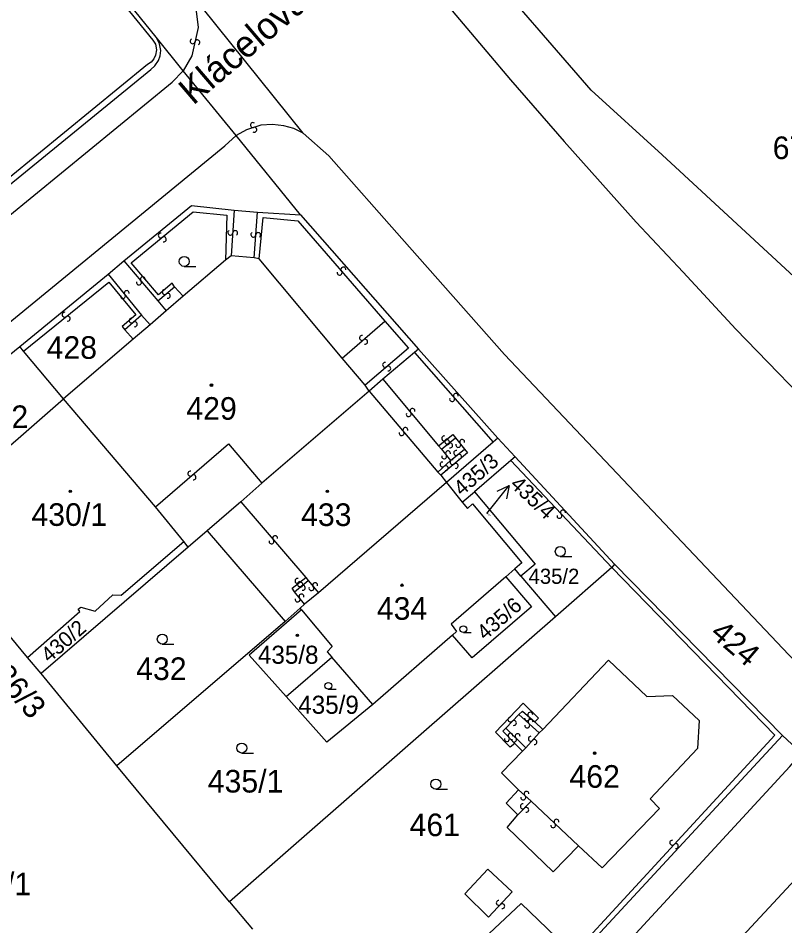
# Model space of a CAD drawing. Extents: x -600391 to -599491, y -1160176 to -1159402.
# Drawn here: x -599909.8 to -599852.1, y -1159960.8 to -1159892.6 of the extents above; entities that cross this region are included whole.
import ezdxf

# ---------------------------------------------------------------- set-up
doc = ezdxf.new("R2010")
doc.units = 0
for name, color, linetype in [('Level 1', 7, 'Continuous'), ('Level 11', 7, 'Continuous'), ('Level 13', 7, 'Continuous'), ('Level 3', 7, 'Continuous'), ('Level 4', 7, 'Continuous'), ('Level 5', 7, 'Continuous'), ('Level 57', 7, 'Continuous')]:
    doc.layers.add(name, color=color, linetype=linetype)

msp = doc.modelspace()

# ---------------------------------------------------------------- linework, layer by layer
at = {"layer": 'Level 1'}
for points in [[(-599773.09, -1160009.38), (-599799.04, -1159987.23), (-599829.62, -1159961.28), (-599837.47, -1159954.27), (-599840.96, -1159951.06), (-599849.35, -1159942.91), (-599851.83, -1159940.43), (-599873.22, -1159917.84), (-599880.94, -1159909.13), (-599886.42, -1159902.9), (-599888.35, -1159901.21), (-599897.08, -1159890.32), (-599918.8, -1159863.43), (-599945.39, -1159830.39)], [(-599904.11, -1159859.22), (-599903.7, -1159859.73), (-599903.4, -1159859.92), (-599878.1, -1159890.84), (-599872.76, -1159897.2), (-599868.72, -1159901.82), (-599863.32, -1159907.89), (-599859.78, -1159911.65), (-599855.8, -1159915.94), (-599848.61, -1159923.35), (-599842.97, -1159928.9)], [(-599899.43, -1159893.99), (-599912.29, -1159878.13), (-599923.65, -1159864.17), (-599926.4, -1159861.06)], [(-599838.86, -1159923.6), (-599861.36, -1159902.83), (-599866.69, -1159897.96), (-599875.35, -1159887.96), (-599866.16, -1159877.35), (-599863.83, -1159879.55), (-599846.25, -1159894.82), (-599845.04, -1159893.23)], [(-599888.35, -1159901.21), (-599897.08, -1159890.32)], [(-599966.31, -1159950.82), (-599928.23, -1159919.57), (-599926.91, -1159918.5), (-599899.82, -1159896.42), (-599899.51, -1159896.14), (-599899.24, -1159895.74), (-599899.13, -1159895.39), (-599899.08, -1159894.99), (-599899.17, -1159894.48), (-599899.43, -1159893.99)], [(-599897.38, -1159896.51), (-599899.43, -1159893.99)], [(-599893.41, -1159901.39), (-599897.38, -1159896.51)], [(-599888.56, -1159907.34), (-599893.41, -1159901.39)], [(-599888.35, -1159901.21), (-599886.42, -1159902.9), (-599880.94, -1159909.13), (-599873.22, -1159917.84), (-599851.83, -1159940.43), (-599849.35, -1159942.91)], [(-599901.85, -1159910.79), (-599896.77, -1159906.65), (-599893.55, -1159906.98)], [(-599893.55, -1159906.98), (-599891.8, -1159907.13)], [(-599891.8, -1159907.13), (-599888.56, -1159907.34)], [(-599888.56, -1159907.34), (-599879.68, -1159917.45)], [(-599893.78, -1159910.43), (-599894.2, -1159910.76)], [(-599892.06, -1159910.57), (-599893.78, -1159910.43)], [(-599891.67, -1159910.64), (-599892.06, -1159910.57)], [(-599885.43, -1159918.13), (-599891.67, -1159910.64)], [(-599903.04, -1159911.8), (-599901.85, -1159910.79)], [(-599894.2, -1159910.76), (-599897.38, -1159913.46)], [(-599909.67, -1159917.25), (-599903.04, -1159911.8)], [(-599897.38, -1159913.46), (-599898.68, -1159914.56)], [(-599898.68, -1159914.56), (-599899.88, -1159915.62)], [(-599899.88, -1159915.62), (-599901.15, -1159916.7)], [(-599901.15, -1159916.7), (-599906.39, -1159921.18)], [(-599917.1, -1159923.33), (-599913.73, -1159920.54), (-599913.44, -1159920.29), (-599911.95, -1159919.06), (-599909.67, -1159917.25)], [(-599909.4, -1159917.59), (-599909.67, -1159917.25)], [(-599879.68, -1159917.45), (-599879.99, -1159917.7)], [(-599879.68, -1159917.45), (-599873.71, -1159924.14)], [(-599906.39, -1159921.18), (-599909.4, -1159917.59)], [(-599883.7, -1159920.14), (-599885.43, -1159918.13)], [(-599879.99, -1159917.7), (-599882.38, -1159919.71)], [(-599883.39, -1159920.59), (-599883.7, -1159920.14)], [(-599882.38, -1159919.71), (-599883.39, -1159920.59)], [(-599883.39, -1159920.59), (-599891.48, -1159927.53)], [(-599913.62, -1159927.46), (-599906.39, -1159921.18)], [(-599899.48, -1159929.31), (-599906.39, -1159921.18)], [(-599873.71, -1159924.14), (-599874.06, -1159924.44)], [(-599873.71, -1159924.14), (-599872.42, -1159925.53)], [(-599874.06, -1159924.44), (-599877.59, -1159927.48)], [(-599872.42, -1159925.53), (-599872.75, -1159925.82)], [(-599872.42, -1159925.53), (-599864.95, -1159933.61)], [(-599872.75, -1159925.82), (-599875.47, -1159928.16)], [(-599891.48, -1159927.53), (-599893.06, -1159928.93)], [(-599877.59, -1159927.48), (-599887.21, -1159935.76)], [(-599877.59, -1159927.48), (-599876.39, -1159928.95)], [(-599876.39, -1159928.95), (-599875.47, -1159928.16)], [(-599875.47, -1159928.16), (-599870.91, -1159933.6), (-599871.99, -1159934.5)], [(-599893.06, -1159928.93), (-599895.58, -1159931.11)], [(-599876.39, -1159928.95), (-599876, -1159929.42), (-599875.62, -1159929.08), (-599871.9, -1159933.51), (-599872.43, -1159933.97)], [(-599897.34, -1159931.91), (-599899.48, -1159929.31)], [(-599895.58, -1159931.11), (-599897.01, -1159932.33)], [(-599895.58, -1159931.11), (-599889.72, -1159937.92)], [(-599909.09, -1159940.63), (-599905.16, -1159937.16), (-599905.3, -1159937), (-599905.09, -1159936.83), (-599904, -1159937.15), (-599902.68, -1159935.92), (-599902.06, -1159935.93), (-599897.34, -1159931.91)], [(-599897.01, -1159932.33), (-599908.07, -1159941.84)], [(-599897.01, -1159932.33), (-599897.34, -1159931.91)], [(-599865.14, -1159933.87), (-599869.39, -1159937.58)], [(-599864.95, -1159933.61), (-599865.14, -1159933.87)], [(-599864.95, -1159933.61), (-599852.3, -1159946.48)], [(-599873.12, -1159934.56), (-599877.23, -1159938.11), (-599876.82, -1159938.68), (-599877.13, -1159938.95)], [(-599873.12, -1159934.56), (-599871.18, -1159936.81), (-599875.66, -1159940.65), (-599877.13, -1159938.95)], [(-599872.43, -1159933.97), (-599873.12, -1159934.56)], [(-599871.99, -1159934.5), (-599872.43, -1159933.97)], [(-599871.99, -1159934.5), (-599869.39, -1159937.58)], [(-599887.21, -1159935.76), (-599888.25, -1159936.62)], [(-599888.25, -1159936.62), (-599888.6, -1159936.91)], [(-599909.09, -1159940.63), (-599912.09, -1159937.04)], [(-599888.5, -1159937.03), (-599892.43, -1159940.44), (-599889.65, -1159943.55)], [(-599888.6, -1159936.91), (-599889.72, -1159937.92)], [(-599888.5, -1159937.03), (-599888.6, -1159936.91)], [(-599888.5, -1159937.03), (-599886.18, -1159939.79), (-599886.56, -1159940.19), (-599886.21, -1159940.59)], [(-599889.72, -1159937.92), (-599902.37, -1159948.76)], [(-599869.39, -1159937.58), (-599879.49, -1159946.39), (-599893.91, -1159959)], [(-599877.13, -1159938.95), (-599883.13, -1159944.15)], [(-599908.07, -1159941.84), (-599909.09, -1159940.63)], [(-599889.65, -1159943.55), (-599886.21, -1159940.59)], [(-599883.13, -1159944.15), (-599886.21, -1159940.59)], [(-599870.33, -1159946.05), (-599865.39, -1159940.83), (-599862.51, -1159943.57), (-599860.57, -1159943.49), (-599858.56, -1159945.36), (-599858.69, -1159947.46), (-599862.26, -1159951.25), (-599861.56, -1159951.99), (-599865.86, -1159956.45), (-599867.65, -1159954.78)], [(-599902.37, -1159948.76), (-599908.07, -1159941.84)], [(-599883.13, -1159944.15), (-599886.59, -1159946.98), (-599889.65, -1159943.55)], [(-599872.45, -1159947.1), (-599872.78, -1159947.37), (-599873.9, -1159946.24), (-599871.82, -1159944.07), (-599870.67, -1159945.19), (-599870.94, -1159945.46)], [(-599870.94, -1159945.46), (-599870.33, -1159946.05)], [(-599852.3, -1159946.48), (-599870.36, -1159965.98)], [(-599852.3, -1159946.48), (-599850.87, -1159947.82)], [(-599871.86, -1159947.66), (-599872.45, -1159947.1)], [(-599872.16, -1159950.58), (-599873.45, -1159949.3), (-599871.86, -1159947.66)], [(-599893.91, -1159959), (-599902.37, -1159948.76)], [(-599872.21, -1159952.46), (-599873.09, -1159951.58), (-599872.16, -1159950.58)], [(-599867.65, -1159954.78), (-599869.56, -1159956.73), (-599873.02, -1159953.4), (-599872.21, -1159952.46)], [(-599893.91, -1159959), (-599892.18, -1159961.06)]]:
    msp.add_lwpolyline(points, dxfattribs=at)
at = {"layer": 'Level 13'}
for centre, start, end in [((-599896.68, -1159894.29), 114.82714, 347.41714), ((-599896.32, -1159894.371), 295.04159, 167.13959), ((-599892.143, -1159900.594), 54.1491, 286.7391), ((-599892.038, -1159900.947), 234.36356, 106.46155), ((-599893.844, -1159908.687), 123.3442, 355.9342), ((-599893.476, -1159908.714), 303.55866, 175.65666), ((-599899.076, -1159908.896), 76.78912, 308.88712), ((-599898.844, -1159909.183), 256.57467, 129.16467), ((-599892.114, -1159908.834), 123.05046, 355.14845), ((-599891.747, -1159908.865), 302.836, 175.426), ((-599885.339, -1159911.451), 348.27846, 220.37646), ((-599900.428, -1159912.193), 347.45617, 219.55416), ((-599885.62, -1159911.69), 168.064, 40.654), ((-599900.711, -1159912.428), 167.24171, 39.83171), ((-599901.923, -1159913.456), 166.44768, 39.03768), ((-599901.636, -1159913.225), 346.66214, 218.76014), ((-599898.778, -1159913.148), 77.48753, 309.58553), ((-599898.542, -1159913.431), 257.27308, 129.86308), ((-599906.304, -1159914.855), 76.27118, 308.36918), ((-599906.075, -1159915.144), 256.05673, 128.64673), ((-599901.27, -1159915.291), 78.27975, 310.86975), ((-599901.03, -1159915.57), 258.49421, 130.59221), ((-599883.939, -1159916.599), 78.17855, 310.27655), ((-599883.7, -1159916.88), 257.96409, 130.55409), ((-599882.199, -1159918.619), 77.49722, 310.08722), ((-599881.962, -1159918.902), 257.71167, 129.80967), ((-599876.88, -1159920.949), 348.71476, 220.81276), ((-599877.159, -1159921.191), 168.50031, 41.09031), ((-599880.421, -1159922.328), 167.19926, 39.78926), ((-599880.138, -1159922.093), 347.41372, 219.51172), ((-599880.951, -1159923.758), 167.33142, 39.92142), ((-599880.668, -1159923.522), 347.54588, 219.64387), ((-599877.754, -1159924.155), 76.0984, 308.19639), ((-599877.535, -1159924.386), 76.42587, 308.52387), ((-599877.525, -1159924.444), 255.88394, 128.47394), ((-599876.403, -1159924.418), 345.29381, 217.39181), ((-599877.305, -1159924.673), 256.21141, 128.80141), ((-599876.696, -1159924.642), 165.07936, 37.66936), ((-599877.755, -1159925.504), 165.49162, 38.08162), ((-599877.464, -1159925.277), 345.70607, 217.80407), ((-599876.856, -1159925.246), 76.69184, 308.78984), ((-599876.624, -1159925.533), 256.47739, 129.06739), ((-599877.882, -1159926.112), 79.26189, 311.35989), ((-599877.638, -1159926.388), 259.04744, 131.63744), ((-599877.118, -1159925.939), 77.21527, 309.80527), ((-599876.883, -1159926.222), 257.42972, 129.52772), ((-599896.849, -1159926.799), 78.12809, 310.22609), ((-599896.61, -1159927.08), 257.91364, 130.50364), ((-599868.815, -1159929.725), 350.76331, 222.86131), ((-599869.084, -1159929.976), 170.54886, 43.13886), ((-599890.75, -1159931.89), 167.99177, 40.58177), ((-599890.469, -1159931.651), 348.20623, 220.30423), ((-599888.794, -1159934.865), 75.89661, 307.99461), ((-599888.616, -1159935.107), 76.90364, 309.00164), ((-599888.566, -1159935.154), 255.68215, 128.27215), ((-599888.383, -1159935.392), 256.68918, 129.27918), ((-599887.457, -1159935.184), 346.99603, 219.09403), ((-599888.486, -1159936.035), 346.11419, 218.70419), ((-599887.742, -1159935.417), 166.78157, 39.37157), ((-599888.774, -1159936.265), 166.32864, 38.42664), ((-599871.277, -1159944.923), 356.01092, 228.10892), ((-599872.772, -1159945.292), 83.81202, 315.91002), ((-599872.507, -1159945.547), 263.59757, 136.18757), ((-599871.522, -1159945.198), 175.79646, 48.38646), ((-599871.255, -1159945.464), 355.30341, 227.4014), ((-599871.504, -1159945.736), 175.08895, 47.67895), ((-599873.035, -1159946.756), 170.80766, 42.90566), ((-599872.766, -1159946.504), 350.59321, 223.18321), ((-599872.49, -1159946.801), 172.94377, 45.04177), ((-599872.231, -1159946.539), 352.72931, 225.31931), ((-599871.237, -1159946.737), 85.89835, 317.99634), ((-599870.963, -1159946.983), 265.68389, 138.27389), ((-599871.557, -1159950.873), 355.30324, 227.89324), ((-599871.84, -1159951.819), 82.65498, 314.75297), ((-599871.804, -1159951.146), 175.51769, 47.61569), ((-599871.58, -1159952.08), 262.44052, 135.03052), ((-599869.303, -1159952.977), 353.90405, 226.49405), ((-599869.558, -1159953.243), 174.11851, 46.21651), ((-599860.595, -1159954.555), 84.51704, 317.10704), ((-599860.325, -1159954.806), 264.73149, 136.82949), ((-599873.654, -1159959.074), 84.18698, 316.77698), ((-599873.386, -1159959.327), 264.40144, 136.49943)]:
    msp.add_arc(centre, 0.184, start, end, dxfattribs=at)
at = {"layer": 'Level 3'}
for points in [[(-599923.93, -1159864.42), (-599912.61, -1159878.33), (-599899.66, -1159894.2), (-599899.47, -1159894.52), (-599899.39, -1159894.94), (-599899.46, -1159895.33), (-599899.59, -1159895.61), (-599899.8, -1159895.87), (-599900.08, -1159896.05), (-599927.16, -1159918.2), (-599934.7, -1159908.99)], [(-599897.08, -1159890.32), (-599896.43, -1159891.82), (-599896.27, -1159893.25), (-599896.74, -1159895.4), (-599897.38, -1159896.51)], [(-599965.6, -1159952.51), (-599964.58, -1159951.97), (-599947.07, -1159937.42), (-599919.05, -1159914.4), (-599898.21, -1159897.38), (-599897.38, -1159896.51)], [(-599888.35, -1159901.21), (-599889.07, -1159900.85), (-599889.81, -1159900.64), (-599890.67, -1159900.54), (-599891.55, -1159900.61), (-599892.63, -1159900.94), (-599893.41, -1159901.39)], [(-599963.03, -1159958.57), (-599943.17, -1159942.28), (-599914.77, -1159918.94), (-599894.25, -1159902.16), (-599893.41, -1159901.39)], [(-599898.03, -1159912.75), (-599898.22, -1159912.49), (-599899.25, -1159913.36), (-599901.29, -1159910.95), (-599896.63, -1159907.12), (-599894.1, -1159907.38), (-599894.2, -1159910.76)], [(-599893.55, -1159906.98), (-599893.78, -1159910.43)], [(-599892.06, -1159910.57), (-599891.8, -1159907.13)], [(-599891.67, -1159910.64), (-599891.36, -1159907.55), (-599888.76, -1159907.79), (-599882.21, -1159915.35)], [(-599901.85, -1159910.79), (-599899.3, -1159913.82)], [(-599903.04, -1159911.8), (-599900.52, -1159914.88)], [(-599909.4, -1159917.59), (-599902.98, -1159912.41), (-599900.95, -1159914.85), (-599901.98, -1159915.74), (-599901.78, -1159915.98)], [(-599899.3, -1159913.82), (-599898.03, -1159912.75)], [(-599897.38, -1159913.46), (-599898.03, -1159912.75)], [(-599899.3, -1159913.82), (-599898.68, -1159914.56)], [(-599900.52, -1159914.88), (-599901.78, -1159915.98)], [(-599900.52, -1159914.88), (-599899.88, -1159915.62)], [(-599885.43, -1159918.13), (-599882.21, -1159915.35)], [(-599882.21, -1159915.35), (-599880.45, -1159917.38), (-599883.7, -1159920.14)], [(-599901.78, -1159915.98), (-599901.15, -1159916.7)], [(-599879.99, -1159917.7), (-599874.06, -1159924.44)], [(-599882.38, -1159919.71), (-599878.17, -1159924.72)], [(-599883.39, -1159920.59), (-599878.24, -1159926.69)], [(-599878.17, -1159924.72), (-599877.11, -1159923.87), (-599876.89, -1159924.1)], [(-599877.95, -1159924.96), (-599876.89, -1159924.1)], [(-599876.89, -1159924.1), (-599876.22, -1159924.96)], [(-599899.48, -1159929.31), (-599893.98, -1159924.57), (-599891.48, -1159927.53)], [(-599878.17, -1159924.72), (-599877.95, -1159924.96)], [(-599876.22, -1159924.96), (-599876, -1159925.23), (-599878.01, -1159926.92)], [(-599877.95, -1159924.96), (-599877.27, -1159925.82)], [(-599877.27, -1159925.82), (-599876.22, -1159924.96)], [(-599878.24, -1159926.69), (-599877.27, -1159925.82)], [(-599872.75, -1159925.82), (-599865.14, -1159933.87)], [(-599878.24, -1159926.69), (-599878.01, -1159926.92)], [(-599878.01, -1159926.92), (-599877.59, -1159927.48)], [(-599893.06, -1159928.93), (-599888.16, -1159934.6)], [(-599865.14, -1159933.87), (-599852.89, -1159946.47), (-599868.02, -1159962.9)], [(-599889.01, -1159935.68), (-599889.19, -1159935.42), (-599888.16, -1159934.6)], [(-599888.16, -1159934.6), (-599887.98, -1159934.83)], [(-599889.01, -1159935.68), (-599887.98, -1159934.83)], [(-599887.98, -1159934.83), (-599887.21, -1159935.76)], [(-599888.25, -1159936.62), (-599889.01, -1159935.68)], [(-599872.15, -1159944.91), (-599871.86, -1159944.65), (-599870.94, -1159945.46)], [(-599873.12, -1159945.93), (-599872.15, -1159944.91)], [(-599872.15, -1159944.91), (-599870.61, -1159946.3)], [(-599872.45, -1159947.1), (-599873.34, -1159946.16), (-599873.12, -1159945.93)], [(-599871.6, -1159947.42), (-599873.12, -1159945.93)], [(-599870.61, -1159946.3), (-599870.33, -1159946.05)], [(-599871.6, -1159947.42), (-599870.61, -1159946.3)], [(-599871.86, -1159947.66), (-599871.6, -1159947.42)], [(-599840.4, -1160038.88), (-599839.99, -1160038.6), (-599839.65, -1160038.21), (-599839.36, -1160037.6), (-599839.27, -1160036.72), (-599839.47, -1160036.06), (-599858.24, -1159989.71), (-599867.79, -1159966.21), (-599851.76, -1159948.82), (-599850.87, -1159947.82)], [(-599871.2, -1159951.44), (-599872.16, -1159950.58)], [(-599872.21, -1159952.46), (-599871.2, -1159951.44)], [(-599867.65, -1159954.78), (-599871.2, -1159951.44)], [(-599846.4, -1159952.01), (-599848.08, -1159953.82), (-599859.23, -1159965.79), (-599859.58, -1159966.58), (-599859.93, -1159967.38), (-599860.05, -1159968.25), (-599859.84, -1159969.13), (-599859.47, -1159970.12), (-599859.1, -1159971.11), (-599852.79, -1159986.79), (-599837.18, -1160025.28), (-599821.6, -1160063.84), (-599805.47, -1160103.79), (-599793.95, -1160133.25), (-599793.45, -1160134.12), (-599792.68, -1160134.75), (-599791.97, -1160134.96), (-599791.42, -1160135), (-599790.84, -1160134.89)], [(-599876.2, -1159958.39), (-599874.47, -1159956.53), (-599872.64, -1159958.25), (-599874.41, -1159960.15), (-599876.2, -1159958.39)], [(-599870.62, -1159965.68), (-599874.76, -1159961.76), (-599871.95, -1159959.12), (-599868.02, -1159962.9)]]:
    msp.add_lwpolyline(points, dxfattribs=at)
at = {"layer": 'Level 5'}
for p, q in [((-599897.31, -1159911.22), (-599896.435, -1159911.22)), ((-599869.02, -1159933.03), (-599868.145, -1159933.03)), ((-599876.31, -1159938.75), (-599875.715, -1159938.75)), ((-599898.96, -1159939.62), (-599898.085, -1159939.62)), ((-599886.47, -1159943.01), (-599885.875, -1159943.01)), ((-599892.98, -1159947.81), (-599892.105, -1159947.81)), ((-599878.38, -1159950.52), (-599877.505, -1159950.52))]:
    msp.add_line(p, q, dxfattribs=at)
for centre, radius in [((-599897.31, -1159910.845), 0.375), ((-599895.26, -1159920.15), 0.09), ((-599895.26, -1159920.15), 0.0521), ((-599905.88, -1159928.13), 0.09), ((-599905.88, -1159928.13), 0.0521), ((-599886.54, -1159928.14), 0.09), ((-599886.54, -1159928.14), 0.0521), ((-599869.02, -1159932.655), 0.375), ((-599880.92, -1159935.19), 0.09), ((-599880.92, -1159935.19), 0.0521), ((-599876.31, -1159938.495), 0.255), ((-599898.96, -1159939.245), 0.375), ((-599888.8, -1159938.96), 0.09), ((-599888.8, -1159938.96), 0.0521), ((-599886.47, -1159942.755), 0.255), ((-599892.98, -1159947.435), 0.375), ((-599866.44, -1159947.82), 0.09), ((-599866.44, -1159947.82), 0.0521), ((-599878.38, -1159950.145), 0.375)]:
    msp.add_circle(centre, radius, dxfattribs=at)
at = {"layer": 'Level 57'}
msp.add_line((-599874.55, -1159929.81), (-599872.86, -1159927.7), dxfattribs=at)
msp.add_lwpolyline([(-599873.775, -1159928.122), (-599872.86, -1159927.7), (-599873.072, -1159928.685)], dxfattribs=at)

# ---------------------------------------------------------------- texts
at = {"layer": 'Level 11'}
msp.add_text('Klácelova', height=2, rotation=40.53151, dxfattribs=at).set_placement((-599896.636, -1159899.15))
at = {"layer": 'Level 4'}
for s, height, p in [('678/1', 1.7, (-599853.04, -1159903.15)), ('428', 1.7, (-599907.667, -1159918.17)), ('429', 1.7, (-599897.149, -1159922.75)), ('430/1', 1.7, (-599908.803, -1159930.73)), ('433', 1.7, (-599888.518, -1159930.74)), ('435/2', 1.14, (-599871.402, -1159935.09)), ('434', 1.7, (-599882.821, -1159937.79)), ('435/8', 1.36, (-599891.762, -1159941.1)), ('432', 1.7, (-599900.926, -1159942.32)), ('435/9', 1.36, (-599888.728, -1159944.86)), ('462', 1.7, (-599868.329, -1159950.42)), ('435/1', 1.7, (-599895.54, -1159950.78)), ('461', 1.7, (-599880.357, -1159954.06)), ('436/1', 1.7, (-599914.509, -1159958.5))]:
    msp.add_text(s, height=height, dxfattribs=at).set_placement(p)
for s, height, rotation, p in [('431/2', 1.7, 1.19997, (-599914.713, -1159923.48)), ('435/3', 1.14, 41.03532, (-599876.431, -1159928.531)), ('435/4', 0.1, 316.40004, (-599874.55, -1159929.81)), ('435/6', 1.14, 41.20002, (-599874.679, -1159939.382)), ('430/2', 1.14, 40.92417, (-599907.469, -1159941.065)), ('424', 1.7, 319.5, (-599857.831, -1159938.948))]:
    msp.add_text(s, height=height, rotation=rotation, dxfattribs=at).set_placement(p)
at = {"layer": 'Level 57'}
for s, height, rotation, p in [('435/4', 1.14, 316.40004, (-599872.86, -1159927.7)), ('436/3', 1.7, 311.4, (-599912.615, -1159941.094))]:
    msp.add_text(s, height=height, rotation=rotation, dxfattribs=at).set_placement(p)

doc.saveas('drawing.dxf')
